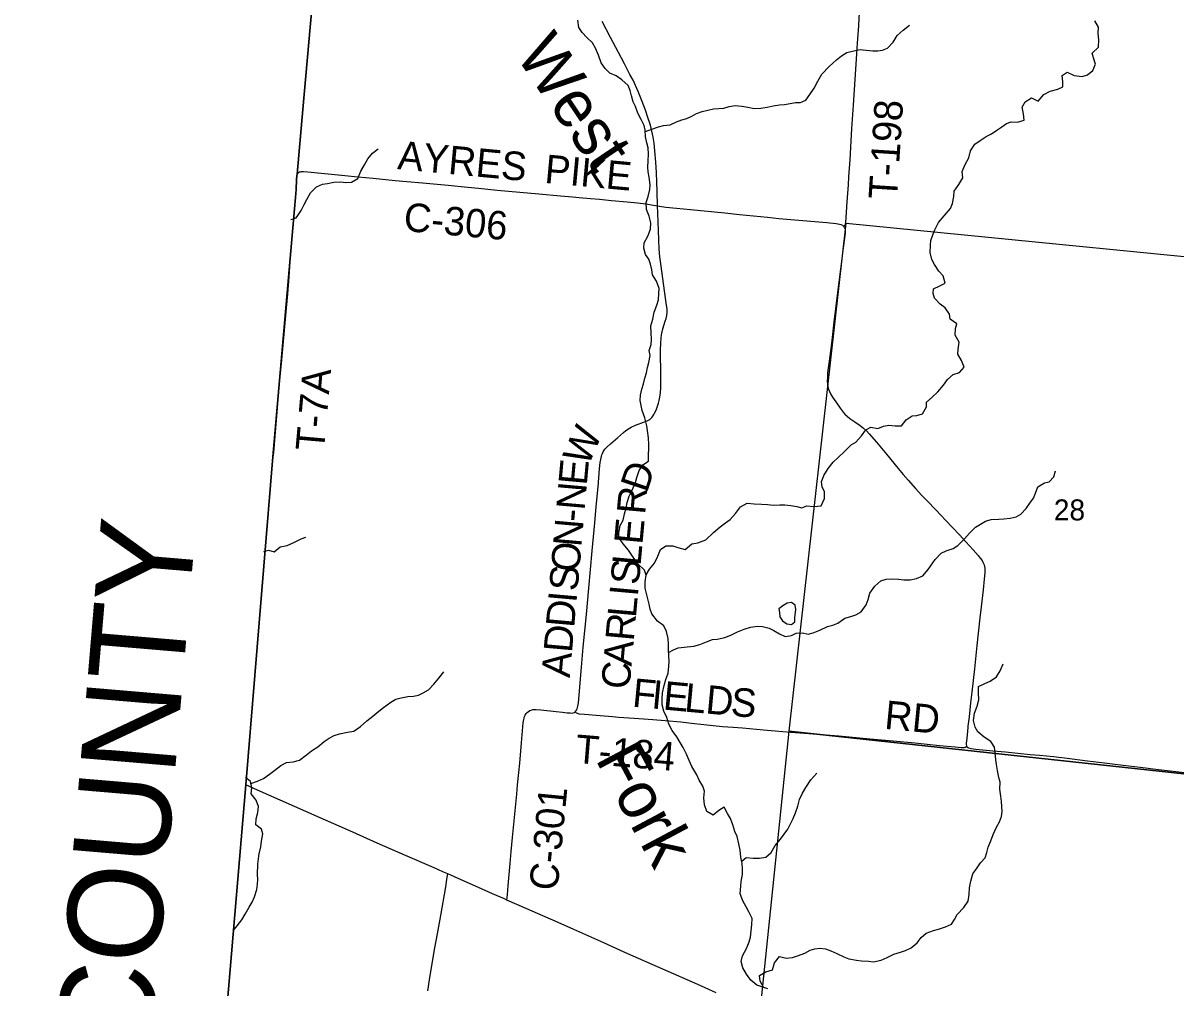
# Model space of a CAD drawing. Extents: x 1410790 to 1770854, y 566777 to 831614.
# Drawn here: x 1535065 to 1547201, y 732945 to 743103 of the extents above; entities that cross this region are included whole.
import ezdxf

# ---------------------------------------------------------------- set-up
doc = ezdxf.new("R2010")
doc.units = 0
for name, color, linetype in [('GM_X_Adjacent_County', 7, 'Continuous'), ('GM_X_Adjacent_County_Text', 7, 'Continuous'), ('GM_X_County', 7, 'Continuous'), ('GM_X_County_Road', 7, 'Continuous'), ('GM_X_County_Road_Text', 7, 'Continuous'), ('GM_X_Minor_Lake', 7, 'Continuous'), ('GM_X_Minor_River', 7, 'Continuous'), ('GM_X_Minor_River_Text', 7, 'Continuous'), ('GM_X_Section', 7, 'Continuous'), ('GM_X_Section_Text', 7, 'Continuous'), ('GM_X_State_Route', 7, 'Continuous'), ('GM_X_Township', 7, 'Continuous'), ('GM_X_Township_Road', 7, 'Continuous'), ('GM_X_Township_Road_Text', 7, 'Continuous')]:
    doc.layers.add(name, color=color, linetype=linetype)

msp = doc.modelspace()

# ---------------------------------------------------------------- linework, layer by layer
at = {"layer": 'GM_X_Adjacent_County'}
msp.add_lwpolyline([(1535644, 714974), (1536110, 720211), (1536441, 723798), (1536443, 723843), (1536575, 725323), (1536893, 729043), (1537162, 732148), (1537410, 735082), (1537695, 738537), (1537924, 741146), (1537933, 741268), (1537939, 741349), (1537945, 741454), (1537947, 741499), (1537952, 741512), (1538010, 742193), (1538385, 746409)], dxfattribs=at)
at = {"layer": 'GM_X_County'}
msp.add_lwpolyline([(1535644, 714974), (1536110, 720211), (1536441, 723798), (1536443, 723843), (1536575, 725323), (1536893, 729043), (1537162, 732148), (1537410, 735082), (1537695, 738537), (1537924, 741146), (1537933, 741268), (1537939, 741349), (1537945, 741454), (1537947, 741499), (1537952, 741512), (1538010, 742193), (1538385, 746409)], dxfattribs=at)
at = {"layer": 'GM_X_County_Road'}
for points in [[(1541745, 741178), (1541740, 741330), (1541732, 741530), (1541726, 741640), (1541716, 741756), (1541707, 741839), (1541698, 741901), (1541685, 741965), (1541669, 742028), (1541643, 742110), (1541616, 742186), (1541581, 742278), (1541539, 742381), (1541486, 742501), (1541454, 742562), (1541395, 742675), (1541332, 742794), (1541250, 742949), (1541163, 743119)], [(1537924, 741146), (1537933, 741268), (1537939, 741349), (1537945, 741454), (1537947, 741499), (1537952, 741512)], [(1537952, 741512), (1537956, 741519), (1537961, 741524), (1537967, 741530), (1537975, 741535), (1537986, 741538), (1537995, 741540), (1538005, 741541), (1538019, 741541), (1538062, 741537), (1538452, 741499), (1538591, 741485), (1538751, 741470), (1538983, 741446), (1539104, 741435), (1539271, 741421), (1539541, 741396), (1539747, 741376), (1539859, 741366), (1540057, 741343), (1540294, 741322), (1540493, 741305), (1540724, 741284), (1540850, 741274), (1540920, 741268), (1541037, 741257), (1541133, 741248), (1541261, 741236), (1541424, 741220), (1541533, 741210), (1541620, 741200), (1541701, 741186), (1541745, 741178)], [(1540877, 735851), (1540882, 735856), (1540892, 735869), (1540898, 735882), (1540903, 735897), (1540906, 735913), (1540911, 735945), (1540943, 736321), (1540962, 736533), (1540995, 736876), (1541021, 737154), (1541057, 737546), (1541083, 737840), (1541095, 737970), (1541106, 738085), (1541119, 738220), (1541135, 738411), (1541141, 738477), (1541146, 738510), (1541153, 738542), (1541158, 738558), (1541164, 738573), (1541171, 738588), (1541191, 738616), (1541213, 738640), (1541250, 738674), (1541324, 738738), (1541386, 738792), (1541412, 738813), (1541440, 738831), (1541468, 738847), (1541514, 738868), (1541608, 738904), (1541635, 738915), (1541650, 738923), (1541662, 738931), (1541673, 738940), (1541687, 738954), (1541695, 738965), (1541704, 738981), (1541713, 738995), (1541729, 739028), (1541745, 739069), (1541755, 739100), (1541763, 739131), (1541769, 739163), (1541775, 739212), (1541778, 739261), (1541778, 739392), (1541777, 739654), (1541779, 739736), (1541783, 739786), (1541787, 739819), (1541793, 739851), (1541801, 739883), (1541825, 739963), (1541835, 739993), (1541842, 740025), (1541845, 740057), (1541844, 740094), (1541840, 740134), (1541819, 740284), (1541782, 740543), (1541770, 740641), (1541763, 740723), (1541754, 740920), (1541748, 741100), (1541745, 741178)], [(1541745, 741178), (1541766, 741174), (1541830, 741165), (1541944, 741154), (1542091, 741141), (1542453, 741106), (1542608, 741089), (1542901, 741059), (1543020, 741047), (1543232, 741027), (1543527, 741002), (1543625, 740992), (1543658, 740987), (1543675, 740982), (1543690, 740975), (1543703, 740963), (1543707, 740957)], [(1543707, 740957), (1543713, 740949), (1543719, 740932), (1543720, 740916), (1543719, 740895), (1543713, 740837), (1543700, 740738), (1543670, 740513), (1543638, 740265), (1543601, 739955), (1543575, 739728), (1543550, 739544), (1543535, 739419), (1543532, 739373), (1543531, 739333), (1543533, 739303), (1543536, 739275), (1543544, 739248), (1543554, 739225), (1543565, 739198), (1543585, 739164), (1543620, 739114), (1543668, 739048), (1543698, 739008), (1543717, 738987), (1543741, 738964), (1543769, 738941), (1543822, 738905), (1543876, 738867), (1543914, 738839), (1543945, 738810), (1543972, 738780), (1544048, 738691), (1544153, 738565), (1544279, 738415), (1544331, 738351), (1544384, 738289), (1544460, 738203), (1544527, 738131), (1544583, 738072), (1544674, 737977), (1544730, 737917), (1544775, 737869), (1544922, 737715), (1544989, 737643), (1545066, 737558), (1545120, 737497), (1545142, 737471), (1545161, 737444), (1545169, 737429), (1545176, 737414), (1545181, 737398), (1545185, 737382), (1545188, 737365), (1545190, 737349), (1545189, 737315), (1545183, 737250), (1545171, 737136), (1545151, 736957), (1545138, 736843), (1545106, 736549), (1545080, 736305), (1545053, 736060), (1545040, 735946), (1545023, 735800), (1545012, 735702), (1545011, 735686), (1544999, 735572), (1544994, 735523), (1544994, 735507), (1544997, 735493), (1544999, 735489)], [(1540159, 733870), (1540164, 733924), (1540173, 734022), (1540193, 734255), (1540205, 734382), (1540219, 734529), (1540240, 734741), (1540263, 734986), (1540271, 735083), (1540284, 735214), (1540293, 735312), (1540312, 735524), (1540331, 735737), (1540336, 735770), (1540340, 735786), (1540345, 735802), (1540351, 735818), (1540360, 735833), (1540372, 735845), (1540385, 735856), (1540399, 735865), (1540415, 735871), (1540432, 735875), (1540448, 735876), (1540465, 735877), (1540515, 735873), (1540678, 735856), (1540743, 735849), (1540792, 735843), (1540824, 735840), (1540844, 735839), (1540857, 735841), (1540870, 735846), (1540877, 735851)], [(1544999, 735489), (1545004, 735481), (1545017, 735473), (1545031, 735468), (1545047, 735465), (1545096, 735459), (1545275, 735442), (1545406, 735430), (1545536, 735416), (1545667, 735404), (1545765, 735395), (1545912, 735380), (1546058, 735363), (1546270, 735337), (1546449, 735316), (1546645, 735291), (1546824, 735269), (1547019, 735245), (1547231, 735219), (1547768, 735151), (1547963, 735127), (1548174, 735100), (1548402, 735073), (1548478, 735065)], [(1539326, 732916), (1539343, 733029), (1539375, 733224), (1539401, 733369), (1539427, 733514), (1539462, 733707), (1539514, 734011), (1539530, 734111), (1539536, 734146)]]:
    msp.add_lwpolyline(points, dxfattribs=at)
at = {"layer": 'GM_X_Minor_Lake'}
for points in [[(1543191, 736814), (1543190, 736842), (1543199, 736930), (1543194, 736974), (1543154, 737003), (1543110, 736995), (1543064, 736968), (1543021, 736937)], [(1543021, 736937), (1543027, 736897), (1543030, 736852), (1543061, 736810), (1543105, 736779), (1543153, 736770), (1543191, 736798), (1543191, 736814)]]:
    msp.add_lwpolyline(points, dxfattribs=at)
at = {"layer": 'GM_X_Minor_River'}
for points in [[(1541383, 737870), (1541396, 737936), (1541415, 738000), (1541425, 738054), (1541447, 738124), (1541476, 738187), (1541513, 738265), (1541528, 738319), (1541551, 738392), (1541588, 738452), (1541648, 738491), (1541649, 738565), (1541654, 738617), (1541651, 738667), (1541648, 738737), (1541639, 738813), (1541630, 738864), (1541611, 738946), (1541581, 739023), (1541572, 739075), (1541560, 739131), (1541565, 739187), (1541578, 739249), (1541597, 739305), (1541612, 739365), (1541627, 739419), (1541638, 739476), (1541653, 739528), (1541666, 739602), (1541655, 739656), (1541678, 739720), (1541682, 739770), (1541676, 739840), (1541675, 739915), (1541696, 739984), (1541707, 740058), (1541736, 740132), (1541755, 740188), (1541758, 740256), (1541761, 740310), (1541732, 740384), (1541691, 740453), (1541684, 740505), (1541671, 740566), (1541652, 740616), (1541619, 740667), (1541600, 740733), (1541605, 740789), (1541642, 740860), (1541669, 740932), (1541672, 741000), (1541657, 741069), (1541628, 741141), (1541625, 741215), (1541644, 741277), (1541663, 741349), (1541666, 741401), (1541655, 741479), (1541644, 741535), (1541641, 741586), (1541644, 741652), (1541649, 741724), (1541644, 741790), (1541633, 741842), (1541618, 741904), (1541615, 741975), (1541602, 742025), (1541571, 742087), (1541538, 742154), (1541511, 742223), (1541486, 742275), (1541469, 742337), (1541456, 742394), (1541435, 742446), (1541368, 742505), (1541310, 742546), (1541243, 742575), (1541192, 742624), (1541151, 742685), (1541122, 742764), (1541091, 742838), (1541058, 742893), (1541001, 742952), (1540950, 743003), (1540917, 743055), (1540906, 743132)], [(1545086, 741827), (1545139, 741868), (1545204, 741907), (1545258, 741935), (1545317, 741974), (1545367, 742009), (1545418, 742046), (1545468, 742063), (1545532, 742060), (1545602, 742079), (1545595, 742146), (1545582, 742216), (1545613, 742275), (1545680, 742316), (1545751, 742281), (1545812, 742350), (1545879, 742385), (1545957, 742406), (1546010, 742431), (1546012, 742485), (1546004, 742550), (1546056, 742587), (1546130, 742552), (1546213, 742540), (1546270, 742559), (1546328, 742603), (1546353, 742670), (1546332, 742735), (1546321, 742785), (1546386, 742850), (1546391, 742926), (1546384, 742994), (1546387, 743060), (1546347, 743127)], [(1541616, 741962), (1541685, 741986), (1541754, 742010), (1541806, 742024), (1541878, 742033), (1541945, 742064), (1541999, 742083), (1542051, 742098), (1542104, 742123), (1542154, 742150), (1542214, 742173), (1542272, 742184), (1542333, 742198), (1542389, 742203), (1542441, 742206), (1542497, 742223), (1542563, 742236), (1542633, 742227), (1542695, 742218), (1542761, 742205), (1542831, 742206), (1542899, 742217), (1542961, 742232), (1543029, 742243), (1543081, 742246), (1543139, 742257), (1543196, 742268), (1543250, 742265), (1543304, 742290), (1543349, 742352), (1543392, 742419), (1543433, 742490), (1543472, 742566), (1543551, 742645), (1543627, 742714), (1543681, 742759), (1543738, 742792), (1543810, 742809), (1543878, 742826), (1543940, 742819), (1544010, 742812), (1544062, 742809), (1544114, 742818), (1544166, 742837), (1544223, 742903), (1544266, 742970), (1544329, 743027), (1544396, 743082)], [(1537883, 741036), (1537913, 741041), (1537940, 741054), (1537958, 741076), (1537993, 741131), (1538026, 741193), (1538051, 741246), (1538092, 741314), (1538155, 741379), (1538217, 741406), (1538271, 741415), (1538337, 741428), (1538407, 741433), (1538463, 741426), (1538523, 741429), (1538588, 741466), (1538621, 741542), (1538660, 741609), (1538695, 741673), (1538742, 741734), (1538805, 741777)], [(1541624, 737295), (1541660, 737353), (1541713, 737418), (1541746, 737492), (1541774, 737562), (1541830, 737601), (1541904, 737601), (1541958, 737581), (1542036, 737561), (1542106, 737620), (1542167, 737631), (1542253, 737662), (1542332, 737741), (1542405, 737800), (1542458, 737841), (1542508, 737878), (1542565, 737941), (1542617, 738011), (1542689, 738048), (1542761, 738043), (1542839, 738037), (1542903, 738036), (1542965, 738027), (1543033, 738030), (1543085, 738031), (1543149, 738024), (1543210, 738013), (1543264, 738000), (1543317, 738020), (1543390, 738012), (1543466, 738019), (1543502, 738097), (1543503, 738169), (1543476, 738219), (1543470, 738272), (1543494, 738341), (1543541, 738413), (1543592, 738480), (1543647, 738531), (1543714, 738594), (1543783, 738663), (1543833, 738692), (1543892, 738758), (1543937, 738821), (1543989, 738850), (1544063, 738833), (1544124, 738858), (1544180, 738871), (1544244, 738862), (1544312, 738861), (1544363, 738926), (1544425, 738967), (1544475, 738973), (1544532, 738990), (1544575, 739061), (1544575, 739111), (1544634, 739166), (1544695, 739222), (1544754, 739291), (1544795, 739352), (1544856, 739403), (1544922, 739424), (1544973, 739481), (1544944, 739550), (1544907, 739617), (1544910, 739671), (1544921, 739745), (1544879, 739816), (1544882, 739886), (1544894, 739937), (1544825, 739985), (1544816, 740037), (1544771, 740104), (1544718, 740143), (1544661, 740206), (1544646, 740256), (1544650, 740306), (1544715, 740335), (1544771, 740364), (1544752, 740440), (1544707, 740491), (1544658, 740560), (1544633, 740613), (1544614, 740687), (1544618, 740763), (1544622, 740815), (1544641, 740873), (1544662, 740925), (1544701, 741002), (1544762, 741073), (1544828, 741150), (1544848, 741202), (1544864, 741278), (1544865, 741332), (1544916, 741403), (1544957, 741473), (1544952, 741539), (1544983, 741615), (1545020, 741684), (1545039, 741758), (1545086, 741827)], [(1541861, 736478), (1541913, 736504), (1541963, 736527), (1542055, 736536), (1542125, 736542), (1542188, 736561), (1542260, 736588), (1542323, 736615), (1542373, 736617), (1542451, 736635), (1542517, 736658), (1542586, 736695), (1542656, 736722), (1542724, 736743), (1542797, 736754), (1542849, 736751), (1542918, 736732), (1542970, 736707), (1543029, 736674), (1543089, 736645), (1543153, 736654), (1543203, 736679), (1543269, 736682), (1543329, 736671), (1543383, 736685), (1543452, 736710), (1543534, 736750), (1543589, 736763), (1543641, 736785), (1543716, 736838), (1543780, 736857), (1543832, 736874), (1543889, 736905), (1543940, 736980), (1543961, 737034), (1543980, 737102), (1544031, 737175), (1544096, 737230), (1544150, 737247), (1544214, 737252), (1544280, 737247), (1544336, 737242), (1544404, 737241), (1544470, 737256), (1544537, 737285), (1544592, 737352), (1544665, 737455), (1544730, 737522), (1544783, 737548), (1544855, 737571), (1544906, 737604), (1544975, 737673), (1545028, 737732), (1545093, 737797), (1545145, 737828), (1545198, 737858), (1545256, 737877), (1545336, 737881), (1545390, 737883), (1545456, 737889), (1545518, 737905), (1545569, 737932), (1545624, 737991), (1545665, 738048), (1545701, 738100), (1545722, 738154), (1545747, 738219), (1545816, 738262), (1545866, 738272), (1545915, 738325), (1545932, 738389)], [(1542906, 732937), (1542843, 732958), (1542789, 732973), (1542726, 733028), (1542681, 733092), (1542642, 733157), (1542625, 733222), (1542640, 733285), (1542679, 733359), (1542710, 733429), (1542723, 733480), (1542730, 733548), (1542737, 733612), (1542740, 733676), (1542705, 733747), (1542678, 733798), (1542643, 733862), (1542614, 733935), (1542621, 734015), (1542626, 734065), (1542637, 734141), (1542640, 734203), (1542635, 734255), (1542622, 734321), (1542613, 734395), (1542599, 734464), (1542584, 734538), (1542557, 734593), (1542536, 734663), (1542511, 734730), (1542480, 734780), (1542445, 734849), (1542388, 734812), (1542329, 734763), (1542264, 734802), (1542239, 734874), (1542230, 734946), (1542239, 735018), (1542222, 735069), (1542181, 735131), (1542158, 735190), (1542105, 735275), (1542076, 735339), (1542050, 735408), (1542015, 735477), (1541981, 735529), (1541948, 735590), (1541899, 735655), (1541863, 735721), (1541842, 735794), (1541809, 735858), (1541792, 735925), (1541793, 735991), (1541798, 736051), (1541815, 736129), (1541830, 736193), (1541855, 736258), (1541862, 736334), (1541865, 736384), (1541862, 736438), (1541861, 736509), (1541860, 736559), (1541857, 736625), (1541840, 736697), (1541811, 736758), (1541744, 736807), (1541685, 736884), (1541666, 736934), (1541657, 736987), (1541643, 737041), (1541628, 737097), (1541615, 737155), (1541614, 737222), (1541625, 737291), (1541606, 737344), (1541539, 737405), (1541488, 737480), (1541438, 737553), (1541383, 737622), (1541336, 737687), (1541336, 737737), (1541352, 737815), (1541383, 737870)], [(1537601, 737538), (1537648, 737553), (1537710, 737536), (1537773, 737589), (1537845, 737602), (1537922, 737637), (1537992, 737672), (1538042, 737691)], [(1542861, 732952), (1542826, 733016), (1542819, 733078), (1542885, 733115), (1542953, 733136), (1542975, 733210), (1543028, 733277), (1543097, 733258), (1543165, 733265), (1543228, 733286), (1543294, 733313), (1543351, 733342), (1543401, 733357), (1543451, 733365), (1543513, 733356), (1543567, 733337), (1543630, 733308), (1543705, 733272), (1543759, 733252), (1543837, 733238), (1543891, 733231), (1543965, 733226), (1544019, 733219), (1544097, 733238), (1544163, 733267), (1544232, 733300), (1544302, 733323), (1544356, 733340), (1544413, 733367), (1544478, 733420), (1544519, 733476), (1544571, 733521), (1544650, 733550), (1544702, 733563), (1544774, 733590), (1544837, 733615), (1544871, 733667), (1544900, 733720), (1544969, 733791), (1545014, 733859), (1545026, 733930), (1545027, 733999), (1545042, 734070), (1545063, 734146), (1545108, 734210), (1545145, 734263), (1545194, 734316), (1545209, 734372), (1545223, 734426), (1545252, 734494), (1545278, 734561), (1545313, 734637), (1545344, 734695), (1545366, 734750), (1545373, 734802), (1545370, 734856), (1545365, 734907), (1545358, 734965), (1545349, 735039), (1545350, 735111), (1545337, 735161), (1545322, 735234), (1545311, 735298), (1545304, 735348), (1545299, 735422), (1545290, 735479), (1545251, 735541), (1545182, 735584), (1545117, 735642), (1545089, 735692), (1545071, 735762), (1545080, 735838), (1545109, 735910), (1545128, 735978), (1545123, 736052), (1545124, 736120), (1545191, 736151), (1545245, 736176), (1545314, 736219), (1545351, 736285), (1545382, 736356)], [(1537464, 735098), (1537532, 735121), (1537598, 735150), (1537661, 735195), (1537716, 735237), (1537778, 735288), (1537839, 735317), (1537909, 735326), (1537977, 735343), (1538050, 735398), (1538103, 735443), (1538168, 735484), (1538236, 735539), (1538289, 735576), (1538339, 735603), (1538398, 735622), (1538480, 735637), (1538548, 735650), (1538617, 735699), (1538684, 735758), (1538748, 735807), (1538809, 735860), (1538860, 735897), (1538937, 735954), (1538991, 735987), (1539047, 736001), (1539114, 736012), (1539176, 736017), (1539228, 736028), (1539278, 736051), (1539333, 736082), (1539390, 736143), (1539441, 736207), (1539496, 736274)], [(1542630, 734281), (1542678, 734318), (1542750, 734313), (1542818, 734310), (1542884, 734323), (1542941, 734372), (1542984, 734446), (1543039, 734513), (1543117, 734616), (1543142, 734667), (1543173, 734729), (1543195, 734787), (1543221, 734859), (1543238, 734930), (1543269, 734996), (1543306, 735055), (1543359, 735137), (1543422, 735206)], [(1537277, 733547), (1537318, 733599), (1537369, 733664), (1537404, 733721), (1537445, 733795), (1537478, 733848), (1537501, 733904), (1537526, 733982), (1537533, 734036), (1537538, 734086), (1537534, 734138), (1537536, 734250), (1537543, 734304), (1537552, 734358), (1537567, 734430), (1537574, 734492), (1537591, 734568), (1537574, 734618), (1537517, 734661), (1537520, 734727), (1537535, 734793), (1537544, 734857), (1537519, 734923), (1537468, 734988), (1537475, 735052), (1537460, 735119), (1537426, 735146), (1537409, 735169)]]:
    msp.add_lwpolyline(points, dxfattribs=at)
at = {"layer": 'GM_X_Section'}
for points in [[(1543730, 740996), (1548998, 740476), (1548486, 735069), (1543130, 735648)], [(1543130, 735648), (1548486, 735069), (1547948, 729722), (1542572, 730250)]]:
    msp.add_lwpolyline(points, close=True, dxfattribs=at)
at = {"layer": 'GM_X_State_Route'}
msp.add_lwpolyline([(1542361, 732895), (1542167, 732982), (1541432, 733306), (1541147, 733433), (1540863, 733561), (1540668, 733647), (1540593, 733680), (1540368, 733778), (1540159, 733870), (1540132, 733882), (1540008, 733936), (1539858, 734003), (1539678, 734083), (1539536, 734146), (1539483, 734169), (1539393, 734208), (1539092, 734339), (1538792, 734471), (1538537, 734584), (1538192, 734736), (1537772, 734922), (1537532, 735028), (1537410, 735082)], dxfattribs=at)
at = {"layer": 'GM_X_Township'}
msp.add_lwpolyline([(1538385, 746409), (1538010, 742193), (1537952, 741512), (1537947, 741499), (1537945, 741454), (1537939, 741349), (1537933, 741268), (1537924, 741146), (1537695, 738537), (1537410, 735082), (1537162, 732148), (1536893, 729043), (1536575, 725323), (1536443, 723843), (1536441, 723798), (1536110, 720211), (1535644, 714974)], dxfattribs=at)
at = {"layer": 'GM_X_Township_Road'}
for points in [[(1543707, 740957), (1543718, 740976), (1543726, 741004), (1543731, 741057), (1543741, 741221), (1543753, 741401), (1543759, 741483), (1543771, 741663), (1543790, 741991), (1543806, 742237), (1543842, 742777), (1543850, 742892), (1543862, 743072), (1543867, 743154), (1543893, 743547), (1543897, 743607)], [(1537698, 738539), (1537700, 738555), (1537707, 738621), (1537721, 738800), (1537735, 738963), (1537763, 739273), (1537786, 739518), (1537803, 739713), (1537831, 740023), (1537851, 740252), (1537865, 740431), (1537882, 740643), (1537902, 740888), (1537924, 741146)], [(1540877, 735851), (1540889, 735843), (1540901, 735837), (1540909, 735834), (1540917, 735832), (1540975, 735826), (1541139, 735813), (1541269, 735802), (1541334, 735797), (1541498, 735785), (1541596, 735778), (1541694, 735770), (1541824, 735760), (1541988, 735746), (1542102, 735733), (1542232, 735718), (1542427, 735698), (1542541, 735689), (1542639, 735682), (1542786, 735670), (1542900, 735660), (1542982, 735652), (1543145, 735639), (1543292, 735627), (1543652, 735598), (1543978, 735568), (1544223, 735547), (1544451, 735525), (1544712, 735499), (1544876, 735483), (1544941, 735476), (1544958, 735476), (1544972, 735477), (1544983, 735480), (1544999, 735489)]]:
    msp.add_lwpolyline(points, dxfattribs=at)

# ---------------------------------------------------------------- texts
at = {"layer": 'GM_X_Adjacent_County_Text'}
msp.add_text('MIAMI COUNTY', height=1000, rotation=85.1528, dxfattribs=at).set_placement((1536052, 727991))
at = {"layer": 'GM_X_County_Road_Text'}
for s, rotation, p in [('AYRES', 354.6182, (1539000, 741566)), ('PIKE', 354.7771, (1540548, 741421)), ('C-306', 354.7825, (1539063, 740916)), ('W', 66.4417, (1541013, 738428)), ('E', 84.8612, (1540999, 738230)), ('D', 71.5685, (1541632, 738150)), ('N', 84.9348, (1540976, 737967)), ('R', 84.8626, (1541613, 737923)), ('-', 84.9341, (1540965, 737844)), ('E', 84.8634, (1541585, 737607)), ('N', 84.9348, (1540942, 737581)), ('O', 84.9339, (1540919, 737318)), ('L', 84.8634, (1541565, 737383)), ('S', 84.8648, (1541547, 737182)), ('S', 84.9339, (1540901, 737116)), ('I', 84.8639, (1541536, 737059)), ('D', 84.9348, (1540866, 736731)), ('I', 84.9341, (1540890, 736994)), ('L', 84.8634, (1541516, 736836)), ('R', 84.8653, (1541493, 736590)), ('D', 84.9335, (1540843, 736468)), ('A', 84.8621, (1541470, 736327)), ('A', 84.9353, (1540820, 736205)), ('C', 84.8646, (1541448, 736082)), ('C-301', 84.5079, (1540691, 733962))]:
    msp.add_text(s, height=300, rotation=rotation, dxfattribs=at).set_placement(p)
at = {"layer": 'GM_X_Minor_River_Text'}
for s, height, rotation, p in [('West', 499.9, 304.0161, (1540239, 742771)), ('Fork', 499.8, 298.0185, (1541084, 735358))]:
    msp.add_text(s, height=height, rotation=rotation, dxfattribs=at).set_placement(p)
at = {"layer": 'GM_X_Section_Text'}
msp.add_text('28', height=221, rotation=0, dxfattribs=at).set_placement((1545916, 737867))
at = {"layer": 'GM_X_Township_Road_Text'}
for s, rotation, p in [('T-198', 86.3544, (1544264, 741240)), ('T-7A', 84.959, (1538232, 738589)), ('F', 354.6707, (1541471, 735907)), ('I', 354.6738, (1541673, 735889)), ('E', 354.6738, (1541795, 735877)), ('L', 354.6696, (1542019, 735856)), ('D', 354.6885, (1542242, 735836)), ('S', 355.242, (1542508, 735811)), ('RD', 354.5822, (1544125, 735674)), ('T-184', 355.3071, (1540872, 735315))]:
    msp.add_text(s, height=300, rotation=rotation, dxfattribs=at).set_placement(p)

doc.saveas('drawing.dxf')
